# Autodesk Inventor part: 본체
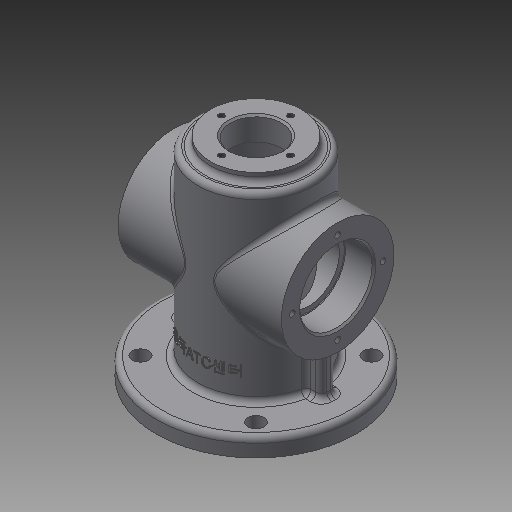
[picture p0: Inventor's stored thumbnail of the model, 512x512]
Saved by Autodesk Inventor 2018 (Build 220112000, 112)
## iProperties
Created: 2020-05
Part Number: 본체
Material: 일반
Document SubType Name: Modeling
Designer: mduedu
Density: 1 g/cm^3
Appearance: 기본값
Mass: 286.81 g
Surface Area: 687.925 cm^2
Volume: 286.81 cm^3
Author: mduedu
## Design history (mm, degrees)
sketch "스케치1"
  geometry: C1 r 32 at (0, 0); 1 further point
  constraints: 1 centre point, 1 coincident
  dimensions: "d0" = 64 diameter of C1
extrude "돌출1" new body sketch "스케치1" distance "d1" = 110; taper "d2" = 0 deg
feature "쉘1" dims "d3" = 8
fillet "모깎기1" dims "d4" = 3
fillet "모깎기2" dims "d5" = 3
sketch "스케치2"
  geometry: C1 r 25 at (0, 0); 1 further point
  constraints: 1 centre point, 1 coincident
  dimensions: "d6" = 50 diameter of C1
extrude "돌출2" join sketch "스케치2" distance "d7" = 5; taper "d8" = 0 deg
sketch "스케치3"
  geometry: C1 r 14 at (0, 0); 1 further point
  constraints: 1 centre point, 1 coincident
  dimensions: "d9" = 28 diameter of C1
extrude "돌출3" cut sketch "스케치3" extent not by distance; stored distance "d10" = 5; taper "d11" = 0 deg
fillet "모깎기3" dims "d12" = 3
sketch "스케치4"
  geometry: C1 r 32 at (0, 0) reference; C2 r 55 at (0, 0); 1 further point
  constraints: 1 centre point, 1 coincident
  dimensions: "d13" = 110 diameter of C2
extrude "돌출4" join sketch "스케치4" distance "d14" = 10; taper "d15" = 0 deg
sketch "스케치5"
  geometry: L1 (0, 0)-(-31.82, 31.82); L2 (0, 0)-(-45, 0); A1 r 45 centre (0, 0) between (-31.82, 31.82) and (-45, 0); 1 further point
  constraints: 4 end point, 2 point on circle, 1 centre point, 1 coincident, 1 horizontal
  dimensions: "d16" = 90 diameter of A1; "d71" = 45 deg angle of L1 L2
hole "구멍1" sketch "스케치5" at (-31.82, 31.82) diameter "d17" = 9; stored, may be unused: countersink angle "d21" = 90 deg, drill point angle "d23" = 118 deg; dims "d18" = 6, "d19" = 4, "d20" = 2, "d22" = 8
fillet "모깎기4" dims "d27" = 3
node "작업 평면1"
sketch "스케치6"
  geometry: L1 (0, 55)-(0, -55) reference; C1 r 31 at (-65, 0); 2 further points
  constraints: 1 centre point, 1 horizontal alignment, 1 midpoint
  dimensions: "d31" = 62 diameter of C1; "d32" = 65 distance from line of C1.centre L1
extrude "돌출5" join sketch "스케치6" stored distance "d33" = 10; taper "d34" = 0 deg
fillet "모깎기5" dims "d35" = 3
sketch "스케치7"
  geometry: C1 r 31 at (0, 0) reference; C2 r 20 at (0, 0); 1 further point
  constraints: 1 centre point, 1 coincident
  dimensions: "d36" = 40 diameter of C2
extrude "돌출6" cut sketch "스케치7" distance "d37" = 16; taper "d38" = 0 deg
sketch "스케치8"
  geometry: C1 r 20 at (0, 0) reference; C2 r 17 at (0, 0); 1 further point
  constraints: 1 centre point, 1 coincident
  dimensions: "d39" = 34 diameter of C2
extrude "돌출7" cut sketch "스케치8" extent not by distance; stored distance "d40" = 15; taper "d41" = 0 deg
fillet "모깎기6" dims "d42" = 0.3
chamfer "모따기1" distance "d43" = 1; stored, may be unused: second distance "d44" = 2, angle "d45" = 45 deg
chamfer "모따기2" distance "d46" = 1; stored, may be unused: second distance "d47" = 2, angle "d48" = 45 deg
sketch "스케치9" dims "d49" = 50
  geometry: C1 r 31 at (0, 0) reference; 3 further points
  constraints: 2 vertical alignment, 1 coincident, 2 other
hole "구멍2" sketch "스케치9" at (0, 25) diameter "d50" = 3.242; stored, may be unused: countersink angle "d54" = 90 deg, drill point angle "d56" = 118 deg; dims "d51" = 7, "d52" = 4, "d53" = 2, "d55" = 9
sketch "스케치10" dims "d60" = 38
  geometry: 3 further points
  constraints: 2 vertical alignment, 1 coincident, 2 other
hole "구멍3" sketch "스케치10" at (0, 19) diameter "d61" = 3.242; stored, may be unused: countersink angle "d65" = 90 deg, drill point angle "d67" = 118 deg; dims "d62" = 8, "d63" = 4, "d64" = 2, "d66" = 10
sketch "스케치11"
  geometry: L1 (32, 31)-(32, 13) reference; L2 (35, 10)-(52, 10) reference; L3 (55, 7)-(55, 0) reference; L4 (55, 0)-(24, 0) reference; L5 (24, 0)-(24, 48) reference; L6 (24, 48)-(29, 48) reference; L7 (29, 48)-(29, 45.3) reference; L8 (29.3, 45)-(44, 45) reference; L9 (44, 45)-(45, 44) reference; L10 (45, 44)-(45, 41.621) reference; L11 (45, 41.621)-(36, 41.621) reference; L12 (36, 41.621)-(35.026, 40) reference; L13 (35.026, 40)-(36, 38.379) reference; L14 (36, 38.379)-(45, 38.379) reference; L15 (45, 38.379)-(45, 34) reference; L16 (45, 34)-(35, 34) reference; L17 (-32, 13)-(-32, 31) reference; L18 (-35, 34)-(-45, 34) reference; L19 (-45, 34)-(-45, 38.379) reference; L20 (-45, 38.379)-(-36, 38.379) reference; L21 (-36, 38.379)-(-35.026, 40) reference; L22 (-35.026, 40)-(-36, 41.621) reference; L23 (-36, 41.621)-(-45, 41.621) reference; L24 (-45, 41.621)-(-45, 44) reference; L25 (-45, 44)-(-44, 45) reference; L26 (-44, 45)-(-29.3, 45) reference; L27 (-29, 45.3)-(-29, 48) reference; L28 (-29, 48)-(-24, 48) reference; L29 (-24, 48)-(-24, 0) reference; L30 (-24, 0)-(-55, 0) reference; L31 (-55, 0)-(-55, 7) reference; L32 (-52, 10)-(-35, 10) reference; L33 (-25, 113)-(-25, 115) reference; L34 (-25, 115)-(-20.621, 115) reference; L35 (-20.621, 115)-(-20.621, 105) reference; L36 (-20.621, 105)-(-19, 104.026) reference; L37 (-19, 104.026)-(-17.379, 105) reference; L38 (-17.379, 105)-(-17.379, 115) reference; L39 (-17.379, 115)-(-15, 115) reference; L40 (-15, 115)-(-14, 114) reference; L41 (-14, 114)-(-14, 102) reference; L42 (-14, 102)-(-21, 102) reference; L43 (-24, 99)-(-24, 82) reference; L44 (-24, 82)-(-29, 82) reference; L45 (-29, 82)-(-29, 84.7) reference; L46 (-29.3, 85)-(-44, 85) reference; L47 (-44, 85)-(-45, 86) reference; L48 (-45, 86)-(-45, 88.379) reference; L49 (-45, 88.379)-(-36, 88.379) reference; L50 (-36, 88.379)-(-35.026, 90) reference; L51 (-35.026, 90)-(-36, 91.621) reference; L52 (-36, 91.621)-(-45, 91.621) reference; L53 (-45, 91.621)-(-45, 96) reference; L54 (-45, 96)-(-35, 96) reference; L55 (-32, 99)-(-32, 107) reference; L56 (-29, 110)-(-28, 110) reference; L57 (28, 110)-(29, 110) reference; L58 (32, 107)-(32, 99) reference; L59 (35, 96)-(45, 96) reference; L60 (45, 96)-(45, 91.621) reference; L61 (45, 91.621)-(36, 91.621) reference; L62 (36, 91.621)-(35.026, 90) reference; L63 (35.026, 90)-(36, 88.379) reference; L64 (36, 88.379)-(45, 88.379) reference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; A1 r 3 centre (35, 13) between (32, 13) and (35, 10) reference; A2 r 3 centre (52, 7) between (55, 7) and (52, 10) reference; A3 r 0.3 centre (29.3, 45.3) between (29, 45.3) and (29.3, 45) reference; A4 r 0.3 centre (-29.3, 45.3) between (-29.3, 45) and (-29, 45.3) reference; A5 r 3 centre (-52, 7) between (-52, 10) and (-55, 7) reference; A6 r 3 centre (-35, 13) between (-35, 10) and (-32, 13) reference; A7 r 3 centre (-28, 113) between (-28, 110) and (-25, 113) reference; A8 r 3 centre (-21, 99) between (-21, 102) and (-24, 99) reference; A9 r 0.3 centre (-29.3, 84.7) between (-29, 84.7) and (-29.3, 85) reference; A10 r 3 centre (-29, 107) between (-29, 110) and (-32, 107) reference; A11 r 3 centre (28, 113) between (25, 113) and (28, 110) reference; A12 r 3 centre (29, 107) between (32, 107) and (29, 110) reference; A13 r 0.3 centre (29.3, 84.7) between (29.3, 85) and (29, 84.7) reference; A14 r 3 centre (21, 99) between (24, 99) and (21, 102) reference; 1 further point
  constraints: 2 end point, 1 midpoint, 1 perpendicular, 1 point on line, 4 other
  dimensions: "d73" = 5 distance between parallel lines of L81 L19
feature "리브1" sketch "스케치11" dims "d74" = 1, "d75" = 8, "d76" = 0, "d77" = 0, "d78" = 1, "d79" = 1
fillet "모깎기7" dims "d80" = 3
fillet "모깎기8" dims "d81" = 3
node "작업 평면2"
sketch "스케치12"
  geometry: 2 further points
  constraints: 1 vertical alignment, 1 other
  dimensions: "d83" = 25 distance of point (0, 25) point (0, 0)
feature "엠보싱1" sketch "스케치12" dims "d0" = 64, "d84" = 0.5, "d85" = 0
node "솔리드1"
pattern_circular "원형 패턴1" dims angle "d25" = 360 deg
mirror "대칭1"
mirror "대칭2"
pattern_circular "원형 패턴2" dims angle "d58" = 360 deg
mirror "대칭3"
pattern_circular "원형 패턴3" dims angle "d69" = 360 deg
mirror "대칭4"
node "투영된 루프1"
node "투영된 루프2"
node "절단 모서리 투영1"
other parameters: "d30" = -45
